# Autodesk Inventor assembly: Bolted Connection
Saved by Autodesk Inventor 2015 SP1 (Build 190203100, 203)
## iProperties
Created: 2011-06
Part Number: Bolted Connection
Document SubType Name: Assembly
Designer: Guilherme Augusto Franco de Souza
ClientObjectVersion: 1
Author: Guilherme Augusto Franco de Souza
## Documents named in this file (1)
- E:\Visitor Experience Project\WSI2015 - Visitor Experience Project\#46- Sheet Metal Technology\01- 3D Models\Outodoor Heater\2- Assemblies\Base\Design Accelerator\Bolted Connection2.iam
